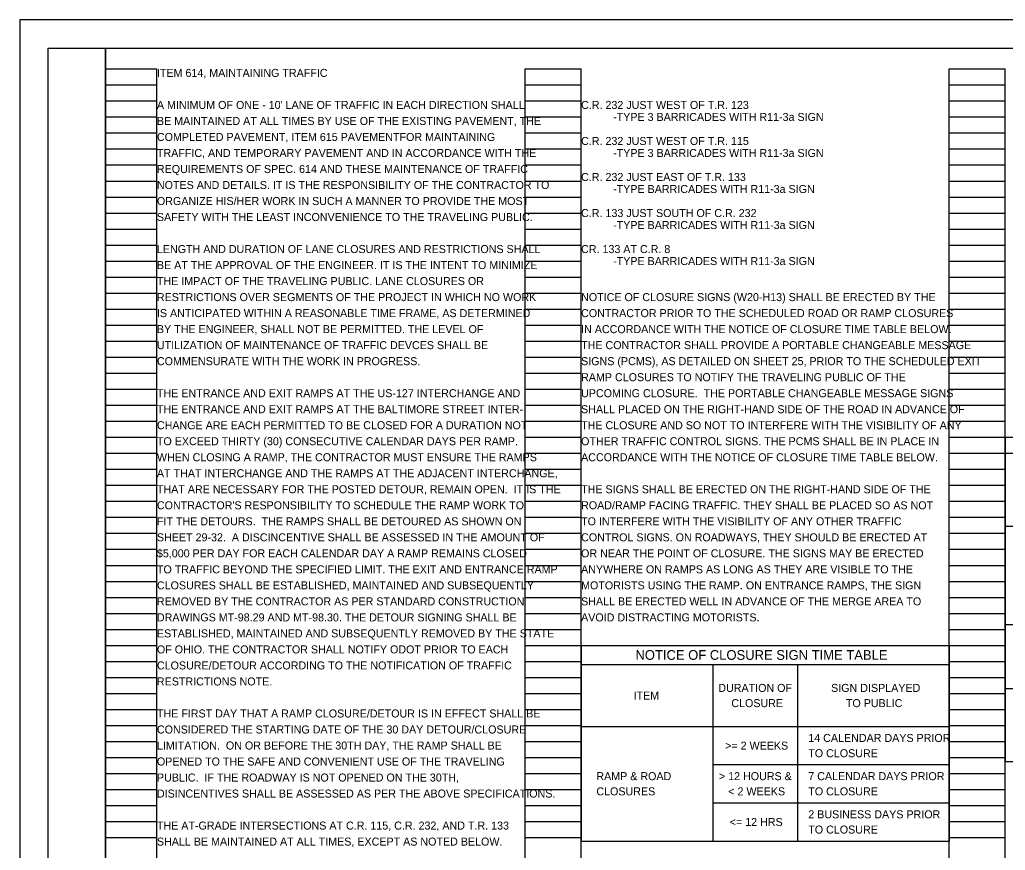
# Model space of a CAD drawing. Extents: x 0 to 34, y 0 to 22.
# Drawn here: x 0 to 17.24, y 7.48 to 22 of the extents above; entities that cross this region are included whole.
import ezdxf

# ---------------------------------------------------------------- set-up
doc = ezdxf.new("R2010")
doc.units = 0
for name, color, linetype in [('Default', 7, 'Continuous'), ('SH_Border', 7, 'Continuous'), ('SH_Cut_Line', 7, 'Continuous'), ('SH_Data', 7, 'Continuous'), ('SH_Text', 7, 'Continuous')]:
    doc.layers.add(name, color=color, linetype=linetype)

msp = doc.modelspace()

# ---------------------------------------------------------------- linework, layer by layer
at = {"layer": 'SH_Border'}
for points in [[(0.5, 21.5), (1.5, 21.5), (1.5, 0.5), (0.5, 0.5)], [(1.5, 21.5), (33.5, 21.5), (33.5, 0.5), (1.5, 0.5)]]:
    msp.add_lwpolyline(points, close=True, dxfattribs=at)
at = {"layer": 'SH_Cut_Line'}
msp.add_lwpolyline([(0, 0), (34, 0), (34, 22), (0, 22)], close=True, dxfattribs=at)
at = {"layer": 'SH_Data'}
for p, q in [((1.5, 0.98), (1.5, 21.14)), ((1.5, 21.14), (2.4, 21.14)), ((2.4, 0.98), (2.4, 21.14)), ((8.84, 0.98), (8.84, 21.14)), ((8.84, 21.14), (9.82, 21.14)), ((9.82, 0.98), (9.82, 21.14)), ((16.26, 0.98), (16.26, 21.14)), ((16.26, 21.14), (17.24, 21.14)), ((17.24, 0.98), (17.24, 21.14)), ((1.5, 20.86), (2.4, 20.86)), ((8.84, 20.86), (9.82, 20.86)), ((16.26, 20.86), (17.24, 20.86)), ((1.5, 20.58), (2.4, 20.58)), ((8.84, 20.58), (9.82, 20.58)), ((16.26, 20.58), (17.24, 20.58)), ((1.5, 20.3), (2.4, 20.3)), ((8.84, 20.3), (9.82, 20.3)), ((16.26, 20.3), (17.24, 20.3)), ((1.5, 20.02), (2.4, 20.02)), ((8.84, 20.02), (9.82, 20.02)), ((16.26, 20.02), (17.24, 20.02)), ((1.5, 19.74), (2.4, 19.74)), ((8.84, 19.74), (9.82, 19.74)), ((16.26, 19.74), (17.24, 19.74)), ((1.5, 19.46), (2.4, 19.46)), ((8.84, 19.46), (9.82, 19.46)), ((16.26, 19.46), (17.24, 19.46)), ((1.5, 19.18), (2.4, 19.18)), ((8.84, 19.18), (9.82, 19.18)), ((16.26, 19.18), (17.24, 19.18)), ((1.5, 18.9), (2.4, 18.9)), ((8.84, 18.9), (9.82, 18.9)), ((16.26, 18.9), (17.24, 18.9)), ((1.5, 18.62), (2.4, 18.62)), ((8.84, 18.62), (9.82, 18.62)), ((16.26, 18.62), (17.24, 18.62)), ((1.5, 18.34), (2.4, 18.34)), ((8.84, 18.34), (9.82, 18.34)), ((16.26, 18.34), (17.24, 18.34)), ((1.5, 18.06), (2.4, 18.06)), ((8.84, 18.06), (9.82, 18.06)), ((16.26, 18.06), (17.24, 18.06)), ((1.5, 17.78), (2.4, 17.78)), ((8.84, 17.78), (9.82, 17.78)), ((16.26, 17.78), (17.24, 17.78)), ((1.5, 17.5), (2.4, 17.5)), ((8.84, 17.5), (9.82, 17.5)), ((16.26, 17.5), (17.24, 17.5)), ((1.5, 17.22), (2.4, 17.22)), ((8.84, 17.22), (9.82, 17.22)), ((16.26, 17.22), (17.24, 17.22)), ((1.5, 16.94), (2.4, 16.94)), ((8.84, 16.94), (9.82, 16.94)), ((16.26, 16.94), (17.24, 16.94)), ((1.5, 16.66), (2.4, 16.66)), ((8.84, 16.66), (9.82, 16.66)), ((16.26, 16.66), (17.24, 16.66)), ((1.5, 16.38), (2.4, 16.38)), ((8.84, 16.38), (9.82, 16.38)), ((16.26, 16.38), (17.24, 16.38)), ((1.5, 16.1), (2.4, 16.1)), ((8.84, 16.1), (9.82, 16.1)), ((16.26, 16.1), (17.24, 16.1)), ((1.5, 15.82), (2.4, 15.82)), ((8.84, 15.82), (9.82, 15.82)), ((16.26, 15.82), (17.24, 15.82)), ((1.5, 15.54), (2.4, 15.54)), ((8.84, 15.54), (9.82, 15.54)), ((16.26, 15.54), (17.24, 15.54)), ((1.5, 15.26), (2.4, 15.26)), ((8.84, 15.26), (9.82, 15.26)), ((16.26, 15.26), (17.24, 15.26)), ((1.5, 14.98), (2.4, 14.98)), ((8.84, 14.98), (9.82, 14.98)), ((16.26, 14.98), (17.24, 14.98)), ((1.5, 14.7), (2.4, 14.7)), ((8.84, 14.7), (9.82, 14.7)), ((16.26, 14.7), (17.24, 14.7)), ((1.5, 14.42), (2.4, 14.42)), ((8.84, 14.42), (9.82, 14.42)), ((16.26, 14.42), (17.24, 14.42)), ((1.5, 14.14), (2.4, 14.14)), ((8.84, 14.14), (9.82, 14.14)), ((16.26, 14.14), (17.24, 14.14)), ((1.5, 13.86), (2.4, 13.86)), ((8.84, 13.86), (9.82, 13.86)), ((16.26, 13.86), (17.24, 13.86)), ((1.5, 13.58), (2.4, 13.58)), ((8.84, 13.58), (9.82, 13.58)), ((16.26, 13.58), (17.24, 13.58)), ((1.5, 13.3), (2.4, 13.3)), ((8.84, 13.3), (9.82, 13.3)), ((16.26, 13.3), (17.24, 13.3)), ((1.5, 13.02), (2.4, 13.02)), ((8.84, 13.02), (9.82, 13.02)), ((16.26, 13.02), (17.24, 13.02)), ((1.5, 12.74), (2.4, 12.74)), ((8.84, 12.74), (9.82, 12.74)), ((16.26, 12.74), (17.24, 12.74)), ((1.5, 12.46), (2.4, 12.46)), ((8.84, 12.46), (9.82, 12.46)), ((16.26, 12.46), (17.24, 12.46)), ((1.5, 12.18), (2.4, 12.18)), ((8.84, 12.18), (9.82, 12.18)), ((16.26, 12.18), (17.24, 12.18)), ((1.5, 11.9), (2.4, 11.9)), ((8.84, 11.9), (9.82, 11.9)), ((16.26, 11.9), (17.24, 11.9)), ((1.5, 11.62), (2.4, 11.62)), ((8.84, 11.62), (9.82, 11.62)), ((16.26, 11.62), (17.24, 11.62)), ((1.5, 11.34), (2.4, 11.34)), ((8.84, 11.34), (9.82, 11.34)), ((16.26, 11.34), (17.24, 11.34)), ((1.5, 11.06), (2.4, 11.06)), ((8.84, 11.06), (9.82, 11.06)), ((16.26, 11.06), (17.24, 11.06)), ((1.5, 10.78), (2.4, 10.78)), ((8.84, 10.78), (9.82, 10.78)), ((16.26, 10.78), (17.24, 10.78)), ((1.5, 10.5), (2.4, 10.5)), ((8.84, 10.5), (9.82, 10.5)), ((16.26, 10.5), (17.24, 10.5)), ((1.5, 10.22), (2.4, 10.22)), ((8.84, 10.22), (9.82, 10.22)), ((16.26, 10.22), (17.24, 10.22)), ((1.5, 9.94), (2.4, 9.94)), ((8.84, 9.94), (9.82, 9.94)), ((16.26, 9.94), (17.24, 9.94)), ((1.5, 9.66), (2.4, 9.66)), ((8.84, 9.66), (9.82, 9.66)), ((16.26, 9.66), (17.24, 9.66)), ((1.5, 9.38), (2.4, 9.38)), ((8.84, 9.38), (9.82, 9.38)), ((16.26, 9.38), (17.24, 9.38)), ((1.5, 9.1), (2.4, 9.1)), ((8.84, 9.1), (9.82, 9.1)), ((16.26, 9.1), (17.24, 9.1)), ((1.5, 8.82), (2.4, 8.82)), ((8.84, 8.82), (9.82, 8.82)), ((16.26, 8.82), (17.24, 8.82)), ((1.5, 8.54), (2.4, 8.54)), ((8.84, 8.54), (9.82, 8.54)), ((16.26, 8.54), (17.24, 8.54)), ((1.5, 8.26), (2.4, 8.26)), ((8.84, 8.26), (9.82, 8.26)), ((16.26, 8.26), (17.24, 8.26)), ((1.5, 7.98), (2.4, 7.98)), ((8.84, 7.98), (9.82, 7.98)), ((16.26, 7.98), (17.24, 7.98)), ((1.5, 7.7), (2.4, 7.7)), ((8.84, 7.7), (9.82, 7.7)), ((16.26, 7.7), (17.24, 7.7))]:
    msp.add_line(p, q, dxfattribs=at)
at = {"layer": 'SH_Text'}
for p, q in [((17.24, 14.7), (23.68, 14.7)), ((17.24, 14.7), (17.24, 9.03)), ((17.24, 14.421), (23.68, 14.421)), ((17.24, 13.143), (23.68, 13.143)), ((17.24, 11.423), (23.68, 11.423)), ((9.82, 11.06), (16.26, 11.06)), ((9.82, 11.06), (9.82, 7.64)), ((16.26, 11.06), (16.26, 7.64)), ((9.82, 10.726), (16.26, 10.726)), ((12.122, 10.726), (12.122, 7.64)), ((13.607, 10.726), (13.607, 7.64)), ((17.24, 10.308), (23.68, 10.308)), ((9.82, 9.642), (16.26, 9.642)), ((12.122, 8.975), (16.26, 8.975)), ((17.24, 9.03), (23.68, 9.03)), ((12.122, 8.307), (16.26, 8.307)), ((9.82, 7.64), (16.26, 7.64))]:
    msp.add_line(p, q, dxfattribs=at)

# ---------------------------------------------------------------- texts
at = {"layer": 'Default'}
for s, p in [('NOTICE OF CLOSURE SIGNS (W20-H13) SHALL BE ERECTED BY THE ', (9.82, 17.08)), ('CONTRACTOR PRIOR TO THE SCHEDULED ROAD OR RAMP CLOSURES ', (9.82, 16.8)), ('IN ACCORDANCE WITH THE NOTICE OF CLOSURE TIME TABLE BELOW.  ', (9.82, 16.52)), ('THE CONTRACTOR SHALL PROVIDE A PORTABLE CHANGEABLE MESSAGE ', (9.82, 16.24)), ('SIGNS (PCMS), AS DETAILED ON SHEET 25, PRIOR TO THE SCHEDULED EXIT ', (9.82, 15.96)), ('RAMP CLOSURES TO NOTIFY THE TRAVELING PUBLIC OF THE ', (9.82, 15.68)), ('UPCOMING CLOSURE.  THE PORTABLE CHANGEABLE MESSAGE SIGNS ', (9.82, 15.4)), ('SHALL PLACED ON THE RIGHT-HAND SIDE OF THE ROAD IN ADVANCE OF ', (9.82, 15.12)), ('THE CLOSURE AND SO NOT TO INTERFERE WITH THE VISIBILITY OF ANY ', (9.82, 14.84)), ('OTHER TRAFFIC CONTROL SIGNS. THE PCMS SHALL BE IN PLACE IN ', (9.82, 14.56)), ('ACCORDANCE WITH THE NOTICE OF CLOSURE TIME TABLE BELOW. ', (9.82, 14.28))]:
    msp.add_text(s, height=0.14, dxfattribs=at).set_placement(p)
at = {"layer": 'SH_Text'}
for s, height, p in [('ITEM 614, MAINTAINING TRAFFIC', 0.14, (2.4, 21)), ("A MINIMUM OF ONE - 10' LANE OF TRAFFIC IN EACH DIRECTION SHALL ", 0.14, (2.4, 20.44)), ('C.R. 232 JUST WEST OF T.R. 123', 0.14, (9.82, 20.44)), ('-TYPE 3 BARRICADES WITH R11-3a SIGN', 0.14, (10.38, 20.23)), ('BE MAINTAINED AT ALL TIMES BY USE OF THE EXISTING PAVEMENT, THE ', 0.14, (2.4, 20.16)), ('COMPLETED PAVEMENT, ITEM 615 PAVEMENTFOR MAINTAINING ', 0.14, (2.4, 19.88)), ('C.R. 232 JUST WEST OF T.R. 115', 0.14, (9.82, 19.81)), ('TRAFFIC, AND TEMPORARY PAVEMENT AND IN ACCORDANCE WITH THE ', 0.14, (2.4, 19.6)), ('-TYPE 3 BARRICADES WITH R11-3a SIGN', 0.14, (10.38, 19.6)), ('REQUIREMENTS OF SPEC. 614 AND THESE MAINTENANCE OF TRAFFIC ', 0.14, (2.4, 19.32)), ('C.R. 232 JUST EAST OF T.R. 133', 0.14, (9.82, 19.18)), ('NOTES AND DETAILS. IT IS THE RESPONSIBILITY OF THE CONTRACTOR TO ', 0.14, (2.4, 19.04)), ('-TYPE BARRICADES WITH R11-3a SIGN', 0.14, (10.38, 18.97)), ('ORGANIZE HIS/HER WORK IN SUCH A MANNER TO PROVIDE THE MOST ', 0.14, (2.4, 18.76)), ('SAFETY WITH THE LEAST INCONVENIENCE TO THE TRAVELING PUBLIC.', 0.14, (2.4, 18.48)), ('C.R. 133 JUST SOUTH OF C.R. 232', 0.14, (9.82, 18.55)), ('-TYPE BARRICADES WITH R11-3a SIGN', 0.14, (10.38, 18.34)), ('LENGTH AND DURATION OF LANE CLOSURES AND RESTRICTIONS SHALL ', 0.14, (2.4, 17.92)), ('CR. 133 AT C.R. 8', 0.14, (9.82, 17.92)), ('BE AT THE APPROVAL OF THE ENGINEER. IT IS THE INTENT TO MINIMIZE ', 0.14, (2.4, 17.64)), ('-TYPE BARRICADES WITH R11-3a SIGN ', 0.14, (10.38, 17.71)), ('THE IMPACT OF THE TRAVELING PUBLIC. LANE CLOSURES OR ', 0.14, (2.4, 17.36)), ('RESTRICTIONS OVER SEGMENTS OF THE PROJECT IN WHICH NO WORK ', 0.14, (2.4, 17.08)), ('IS ANTICIPATED WITHIN A REASONABLE TIME FRAME, AS DETERMINED ', 0.14, (2.4, 16.8)), ('BY THE ENGINEER, SHALL NOT BE PERMITTED. THE LEVEL OF ', 0.14, (2.4, 16.52)), ('UTILIZATION OF MAINTENANCE OF TRAFFIC DEVCES SHALL BE ', 0.14, (2.4, 16.24)), ('COMMENSURATE WITH THE WORK IN PROGRESS.', 0.14, (2.4, 15.96)), ('THE ENTRANCE AND EXIT RAMPS AT THE US-127 INTERCHANGE AND', 0.14, (2.4, 15.4)), ('THE ENTRANCE AND EXIT RAMPS AT THE BALTIMORE STREET INTER-', 0.14, (2.4, 15.12)), ('CHANGE ARE EACH PERMITTED TO BE CLOSED FOR A DURATION NOT ', 0.14, (2.4, 14.84)), ('TO EXCEED THIRTY (30) CONSECUTIVE CALENDAR DAYS PER RAMP. ', 0.14, (2.4, 14.56)), ('WHEN CLOSING A RAMP, THE CONTRACTOR MUST ENSURE THE RAMPS ', 0.14, (2.4, 14.28)), ('AT THAT INTERCHANGE AND THE RAMPS AT THE ADJACENT INTERCHANGE, ', 0.14, (2.4, 14)), ('THAT ARE NECESSARY FOR THE POSTED DETOUR, REMAIN OPEN.  IT IS THE', 0.14, (2.4, 13.72)), ('THE SIGNS SHALL BE ERECTED ON THE RIGHT-HAND SIDE OF THE', 0.14, (9.82, 13.72)), ("CONTRACTOR'S RESPONSIBILITY TO SCHEDULE THE RAMP WORK TO ", 0.14, (2.4, 13.44)), ('ROAD/RAMP FACING TRAFFIC. THEY SHALL BE PLACED SO AS NOT', 0.14, (9.82, 13.44)), ('FIT THE DETOURS.  THE RAMPS SHALL BE DETOURED AS SHOWN ON ', 0.14, (2.4, 13.16)), ('TO INTERFERE WITH THE VISIBILITY OF ANY OTHER TRAFFIC', 0.14, (9.82, 13.16)), ('SHEET 29-32.  A DISCINCENTIVE SHALL BE ASSESSED IN THE AMOUNT OF ', 0.14, (2.4, 12.88)), ('CONTROL SIGNS. ON ROADWAYS, THEY SHOULD BE ERECTED AT', 0.14, (9.82, 12.88)), ('$5,000 PER DAY FOR EACH CALENDAR DAY A RAMP REMAINS CLOSED', 0.14, (2.4, 12.6)), ('OR NEAR THE POINT OF CLOSURE. THE SIGNS MAY BE ERECTED', 0.14, (9.82, 12.6)), ('TO TRAFFIC BEYOND THE SPECIFIED LIMIT. THE EXIT AND ENTRANCE RAMP ', 0.14, (2.4, 12.32)), ('ANYWHERE ON RAMPS AS LONG AS THEY ARE VISIBLE TO THE', 0.14, (9.82, 12.32)), ('CLOSURES SHALL BE ESTABLISHED, MAINTAINED AND SUBSEQUENTLY ', 0.14, (2.4, 12.04)), ('MOTORISTS USING THE RAMP. ON ENTRANCE RAMPS, THE SIGN', 0.14, (9.82, 12.04)), ('REMOVED BY THE CONTRACTOR AS PER STANDARD CONSTRUCTION ', 0.14, (2.4, 11.76)), ('SHALL BE ERECTED WELL IN ADVANCE OF THE MERGE AREA TO', 0.14, (9.82, 11.76)), ('DRAWINGS MT-98.29 AND MT-98.30. THE DETOUR SIGNING SHALL BE ', 0.14, (2.4, 11.48)), ('AVOID DISTRACTING MOTORISTS.', 0.14, (9.82, 11.48)), ('ESTABLISHED, MAINTAINED AND SUBSEQUENTLY REMOVED BY THE STATE ', 0.14, (2.4, 11.2)), ('OF OHIO. THE CONTRACTOR SHALL NOTIFY ODOT PRIOR TO EACH ', 0.14, (2.4, 10.92)), ('NOTICE OF CLOSURE SIGN TIME TABLE', 0.17, (10.771, 10.808)), ('CLOSURE/DETOUR ACCORDING TO THE NOTIFICATION OF TRAFFIC ', 0.14, (2.4, 10.64)), ('RESTRICTIONS NOTE.', 0.14, (2.4, 10.36)), ('DURATION OF ', 0.14, (12.22, 10.247)), ('SIGN DISPLAYED ', 0.14, (14.193, 10.247)), ('ITEM', 0.14, (10.737, 10.114)), ('CLOSURE', 0.14, (12.448, 9.981)), ('TO PUBLIC', 0.14, (14.452, 9.981)), ('THE FIRST DAY THAT A RAMP CLOSURE/DETOUR IS IN EFFECT SHALL BE ', 0.14, (2.4, 9.8)), ('CONSIDERED THE STARTING DATE OF THE 30 DAY DETOUR/CLOSURE ', 0.14, (2.4, 9.52)), ('14 CALENDAR DAYS PRIOR ', 0.14, (13.794, 9.372)), ('LIMITATION.  ON OR BEFORE THE 30TH DAY, THE RAMP SHALL BE ', 0.14, (2.4, 9.24)), ('>= 2 WEEKS', 0.14, (12.34, 9.238)), ('TO CLOSURE', 0.14, (13.794, 9.105)), ('OPENED TO THE SAFE AND CONVENIENT USE OF THE TRAVELING ', 0.14, (2.4, 8.96)), ('PUBLIC.  IF THE ROADWAY IS NOT OPENED ON THE 30TH, ', 0.14, (2.4, 8.68)), ('RAMP & ROAD ', 0.14, (10.087, 8.704)), ('> 12 HOURS & ', 0.14, (12.231, 8.704)), ('7 CALENDAR DAYS PRIOR ', 0.14, (13.794, 8.704)), ('DISINCENTIVES SHALL BE ASSESSED AS PER THE ABOVE SPECIFICATIONS. ', 0.14, (2.4, 8.4)), ('CLOSURES', 0.14, (10.087, 8.438)), ('< 2 WEEKS', 0.14, (12.395, 8.438)), ('TO CLOSURE', 0.14, (13.794, 8.438)), ('2 BUSINESS DAYS PRIOR ', 0.14, (13.794, 8.037)), ('THE AT-GRADE INTERSECTIONS AT C.R. 115, C.R. 232, AND T.R. 133', 0.14, (2.4, 7.84)), ('<= 12 HRS', 0.14, (12.42, 7.903)), ('TO CLOSURE', 0.14, (13.794, 7.77)), ('SHALL BE MAINTAINED AT ALL TIMES, EXCEPT AS NOTED BELOW. ', 0.14, (2.4, 7.56))]:
    msp.add_text(s, height=height, dxfattribs=at).set_placement(p)

doc.saveas('drawing.dxf')
